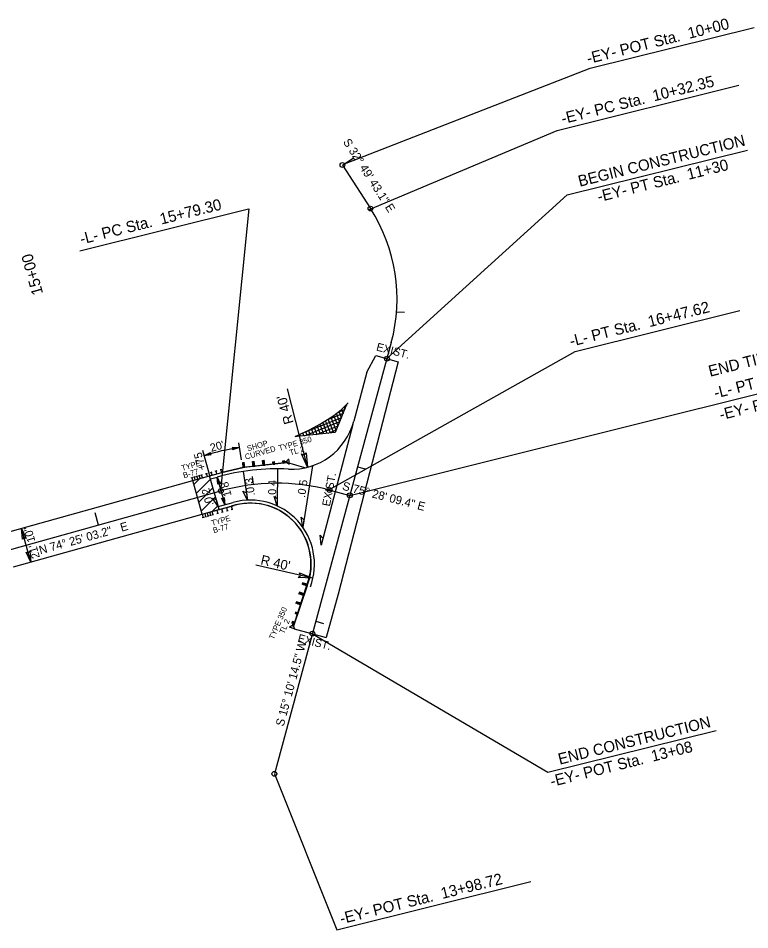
# Model space of a CAD drawing. Extents: x 1030774 to 1032138, y 656382 to 657027.
# Drawn here: x 1031349 to 1031806, y 656458 to 657027 of the extents above; entities that cross this region are included whole.
import ezdxf

# ---------------------------------------------------------------- set-up
doc = ezdxf.new("R2010")
doc.units = 0
for name, color, linetype in [('Default', 7, 'Continuous'), ('Exist Horizontal Alignment', 7, 'Continuous'), ('Exist Horizontal Alignment Direction Label', 7, 'Continuous'), ('Exist Horizontal Alignment Station Label', 7, 'Continuous'), ('Exist Horizontal Alignment Tick Large', 7, 'Continuous'), ('Exist Horizontal Alignment Tick Small', 7, 'Continuous'), ('Prop Approach Slab', 7, 'Continuous'), ('Prop Approach Slab Hatching', 7, 'Continuous'), ('Prop Dimension', 7, 'Continuous'), ('Prop Dimension Text', 7, 'Continuous'), ('Prop EOT', 7, 'Continuous'), ('Prop Guardrail', 7, 'Continuous'), ('Prop Guardrail Anchor Unit CELL', 7, 'Continuous'), ('Prop Horizontal Alignment', 7, 'Continuous'), ('Prop Horizontal Alignment Direction Label', 7, 'Continuous'), ('Prop Horizontal Alignment Station Label', 7, 'Continuous'), ('Prop Horizontal Alignment Tick Label', 7, 'Continuous'), ('Prop Horizontal Alignment Tick Large', 7, 'Continuous'), ('Prop Horizontal Alignment Tick Small', 7, 'Continuous'), ('Prop Paved Shoulder', 7, 'Continuous'), ('Prop Rem of Exist Conc Pvmt', 7, 'Continuous'), ('Prop Roadway Bridge', 7, 'Continuous'), ('Prop Structure Anchor Unit CELL', 7, 'Continuous'), ('Prop Superelevation  Arrow CELL', 7, 'Continuous'), ('Prop Superelevation Label', 7, 'Continuous'), ('Prop Terminator CELL', 7, 'Continuous')]:
    doc.layers.add(name, color=color, linetype=linetype)

msp = doc.modelspace()

# ---------------------------------------------------------------- linework, layer by layer
at = {"layer": 'Default'}
for p, q in [((1031529.48, 656746.41), (1031517.01, 656795.51)), ((1031532.88, 656677.08), (1031497.21, 656685.17))]:
    msp.add_line(p, q, dxfattribs=at)
at = {"layer": 'Exist Horizontal Alignment'}
for p, q in [((1031551.32, 656935.2), (1031568.86, 656908.01)), ((1031581.87, 656824.27), (1031508.83, 656554.91))]:
    msp.add_line(p, q, dxfattribs=at)
msp.add_arc((1031481.33, 656851.54), 104.17, 344.8293, 32.8286, dxfattribs=at)
at = {"layer": 'Exist Horizontal Alignment Station Label'}
for p, q in [((1031706.16, 656995.66), (1031808.52, 657021.19)), ((1031552.58, 656936.01), (1031706.16, 656995.66)), ((1031685.54, 656956.84), (1031799.08, 656985.15)), ((1031567.6, 656907.2), (1031685.54, 656956.84)), ((1031691.81, 656916.51), (1031804.37, 656944.57)), ((1031579.16, 656814.26), (1031691.81, 656916.51)), ((1031532.57, 656642.46), (1031679.65, 656555.88)), ((1031679.65, 656555.88), (1031784.83, 656582.1)), ((1031508.83, 656554.91), (1031547.88, 656457.53)), ((1031547.88, 656457.53), (1031669.1, 656487.76))]:
    msp.add_line(p, q, dxfattribs=at)
for centre in [(1031551.32, 656935.2), (1031568.86, 656908.01), (1031579.16, 656814.26), (1031532.59, 656642.52), (1031508.83, 656554.91)]:
    msp.add_circle(centre, 1.5, dxfattribs=at)
at = {"layer": 'Exist Horizontal Alignment Tick Large'}
msp.add_line((1031551.32, 656935.2), (1031558.05, 656939.54), dxfattribs=at)
at = {"layer": 'Exist Horizontal Alignment Tick Small'}
for p, q in [((1031585.2, 656843.59), (1031590.18, 656843.21)), ((1031560.84, 656746.7), (1031565.66, 656745.39)), ((1031534.67, 656650.19), (1031539.49, 656648.88))]:
    msp.add_line(p, q, dxfattribs=at)
at = {"layer": 'Prop Approach Slab'}
for p, q in [((1031457.91, 656738.11), (1031468.32, 656741.01)), ((1031474.23, 656719.99), (1031468.37, 656741.02)), ((1031463.78, 656717.07), (1031474.19, 656719.97))]:
    msp.add_line(p, q, dxfattribs=at)
at = {"layer": 'Prop Approach Slab Hatching'}
for p, q in [((1031458.57, 656735.74), (1031462.11, 656739.28)), ((1031460.11, 656730.21), (1031468.93, 656739.02)), ((1031461.65, 656724.68), (1031470.47, 656733.49)), ((1031463.2, 656719.15), (1031472.01, 656727.96)), ((1031469.89, 656718.77), (1031473.55, 656722.43))]:
    msp.add_line(p, q, dxfattribs=at)
at = {"layer": 'Prop Dimension'}
for p, q in [((1031472.98, 656740.32), (1031477.81, 656722.98)), ((1031356.66, 656687.2), (1031350.8, 656708.24))]:
    msp.add_line(p, q, dxfattribs=at)
at = {"layer": 'Prop EOT'}
for p, q in [((1031566.68, 656805.86), (1031572.16, 656816.16)), ((1031572.16, 656816.16), (1031586.18, 656812.36)), ((1031586.18, 656812.36), (1031548.7, 656667.1)), ((1031566.68, 656805.86), (1031558.38, 656775.25)), ((1031468.88, 656739.17), (1031472.98, 656740.32)), ((1031473.72, 656721.84), (1031483.13, 656724.46)), ((1031529.38, 656672.34), (1031520.75, 656647.22)), ((1031548.7, 656667.1), (1031541.2, 656640.12)), ((1031521.11, 656645.57), (1031541.2, 656640.12))]:
    msp.add_line(p, q, dxfattribs=at)
for centre, radius, start, end in [((1031519.63, 656785.18), 40, 267.0173, 345.6251), ((1031510.32, 656606.42), 139, 87.0173, 105.5824), ((1031493.88, 656685.93), 40, 339.3432, 105.5824), ((1031493.88, 656685.93), 38, 339.0563, 105.5824)]:
    msp.add_arc(centre, radius, start, end, dxfattribs=at)
at = {"layer": 'Prop Guardrail'}
msp.add_line((1031489.38, 656746.29), (1031475.97, 656743.14), dxfattribs=at)
for centre, radius, start, end in [((1031443.03, 656712.42), 40, 14, 14), ((1031501.41, 656687.22), 40, 119.2937, 119.2937), ((1031493.83, 656686.23), 37.82, 340.0066, 108.4837)]:
    msp.add_arc(centre, radius, start, end, dxfattribs=at)
at = {"layer": 'Prop Guardrail Anchor Unit CELL'}
for p, q in [((1031501.47, 656750.67), (1031502.47, 656750.78)), ((1031502.47, 656750.78), (1031501.64, 656749.17)), ((1031502.8, 656747.77), (1031502.47, 656750.78)), ((1031517.62, 656751.5), (1031516.55, 656750.52)), ((1031517.62, 656751.5), (1031517.93, 656751.53)), ((1031518.25, 656748.61), (1031517.93, 656751.53)), ((1031489.05, 656749.31), (1031490.04, 656749.42)), ((1031489.38, 656746.29), (1031489.05, 656749.31)), ((1031490.21, 656747.91), (1031489.05, 656749.31)), ((1031490.04, 656749.42), (1031489.21, 656747.8)), ((1031489.21, 656747.8), (1031490.21, 656747.91)), ((1031489.21, 656747.8), (1031490.37, 656746.4)), ((1031489.38, 656746.29), (1031490.21, 656747.91)), ((1031489.38, 656746.29), (1031490.37, 656746.4)), ((1031514.72, 656749.07), (1031489.87, 656746.35)), ((1031490.37, 656746.4), (1031490.04, 656749.42)), ((1031495.26, 656749.99), (1031496.25, 656750.1)), ((1031495.59, 656746.98), (1031495.26, 656749.99)), ((1031496.42, 656748.59), (1031495.26, 656749.99)), ((1031496.25, 656750.1), (1031495.42, 656748.48)), ((1031495.42, 656748.48), (1031496.42, 656748.59)), ((1031495.42, 656748.48), (1031496.58, 656747.08)), ((1031495.59, 656746.98), (1031496.42, 656748.59)), ((1031495.59, 656746.98), (1031496.58, 656747.08)), ((1031496.58, 656747.08), (1031496.25, 656750.1)), ((1031501.8, 656747.66), (1031501.47, 656750.67)), ((1031502.63, 656749.27), (1031501.47, 656750.67)), ((1031501.64, 656749.17), (1031502.63, 656749.27)), ((1031501.64, 656749.17), (1031502.8, 656747.77)), ((1031501.8, 656747.66), (1031502.63, 656749.27)), ((1031501.8, 656747.66), (1031502.8, 656747.77)), ((1031507.85, 656749.85), (1031508.84, 656749.96)), ((1031508.01, 656748.34), (1031507.85, 656749.85)), ((1031507.85, 656749.85), (1031509.01, 656748.45)), ((1031508.01, 656748.34), (1031508.84, 656749.96)), ((1031508.01, 656748.34), (1031509.01, 656748.45)), ((1031509.01, 656748.45), (1031508.84, 656749.96)), ((1031514.06, 656750.53), (1031515.06, 656750.64)), ((1031514.23, 656749.02), (1031514.06, 656750.53)), ((1031514.06, 656750.53), (1031515.22, 656749.13)), ((1031514.23, 656749.02), (1031515.06, 656750.64)), ((1031514.23, 656749.02), (1031515.22, 656749.13)), ((1031515.22, 656749.13), (1031515.06, 656750.64)), ((1031516.6, 656750.02), (1031515.14, 656749.85)), ((1031515.22, 656749.14), (1031516.68, 656749.3)), ((1031516.55, 656750.52), (1031516.68, 656749.3)), ((1031516.68, 656749.3), (1031517.95, 656748.57)), ((1031517.95, 656748.57), (1031518.25, 656748.61)), ((1031521.38, 656649.09), (1031529.2, 656672.83)), ((1031526.47, 656674.26), (1031526.16, 656673.31)), ((1031526.16, 656673.31), (1031527.91, 656673.78)), ((1031529.04, 656672.36), (1031526.16, 656673.31)), ((1031529.36, 656673.31), (1031526.47, 656674.26)), ((1031527.6, 656672.83), (1031526.47, 656674.26)), ((1031527.91, 656673.78), (1031527.6, 656672.83)), ((1031529.36, 656673.31), (1031527.6, 656672.83)), ((1031527.91, 656673.78), (1031529.04, 656672.36)), ((1031529.36, 656673.31), (1031529.04, 656672.36)), ((1031524.52, 656668.32), (1031524.2, 656667.37)), ((1031524.2, 656667.37), (1031525.96, 656667.84)), ((1031527.09, 656666.42), (1031524.2, 656667.37)), ((1031527.4, 656667.37), (1031524.52, 656668.32)), ((1031525.64, 656666.89), (1031524.52, 656668.32)), ((1031525.96, 656667.84), (1031525.64, 656666.89)), ((1031527.4, 656667.37), (1031525.64, 656666.89)), ((1031525.96, 656667.84), (1031527.09, 656666.42)), ((1031527.4, 656667.37), (1031527.09, 656666.42)), ((1031522.56, 656662.38), (1031522.25, 656661.43)), ((1031522.25, 656661.43), (1031524, 656661.91)), ((1031525.13, 656660.48), (1031522.25, 656661.43)), ((1031525.44, 656661.43), (1031522.56, 656662.38)), ((1031523.69, 656660.96), (1031522.56, 656662.38)), ((1031524, 656661.91), (1031523.69, 656660.96)), ((1031525.44, 656661.43), (1031523.69, 656660.96)), ((1031524, 656661.91), (1031525.13, 656660.48)), ((1031525.44, 656661.43), (1031525.13, 656660.48)), ((1031522.05, 656655.97), (1031521.73, 656655.02)), ((1031523.49, 656655.5), (1031521.73, 656655.02)), ((1031523.17, 656654.55), (1031521.73, 656655.02)), ((1031523.49, 656655.5), (1031522.05, 656655.97)), ((1031522.05, 656655.97), (1031523.17, 656654.55)), ((1031523.49, 656655.5), (1031523.17, 656654.55)), ((1031520.09, 656650.04), (1031519.78, 656649.09)), ((1031521.53, 656649.56), (1031519.78, 656649.09)), ((1031521.22, 656648.61), (1031519.78, 656649.09)), ((1031520.06, 656647.44), (1031520.53, 656648.84)), ((1031521.53, 656649.56), (1031520.09, 656650.04)), ((1031520.09, 656650.04), (1031521.22, 656648.61)), ((1031521.21, 656648.61), (1031520.75, 656647.22)), ((1031521.53, 656649.56), (1031521.22, 656648.61)), ((1031518.4, 656646.76), (1031518.31, 656646.46)), ((1031521.1, 656645.54), (1031518.31, 656646.46)), ((1031518.4, 656646.76), (1031519.58, 656647.6)), ((1031519.58, 656647.6), (1031520.75, 656647.22)), ((1031520.75, 656647.22), (1031521.19, 656645.83)), ((1031521.19, 656645.83), (1031521.1, 656645.54))]:
    msp.add_line(p, q, dxfattribs=at)
at = {"layer": 'Prop Horizontal Alignment'}
for p, q in [((1031310.74, 656685.73), (1031475.4, 656731.65)), ((1031542.93, 656732.27), (1031556, 656728.88))]:
    msp.add_line(p, q, dxfattribs=at)
msp.add_arc((1031510.32, 656606.42), 130, 75.4693, 105.5824, dxfattribs=at)
at = {"layer": 'Prop Horizontal Alignment Station Label'}
for p, q in [((1031387.2, 656881.59), (1031492.71, 656907.9)), ((1031475.4, 656731.65), (1031493.07, 656907.81)), ((1031696.82, 656818.8), (1031799.62, 656844.43)), ((1031556, 656728.88), (1031931.5, 656822.46)), ((1031542.93, 656732.27), (1031696.82, 656818.8))]:
    msp.add_line(p, q, dxfattribs=at)
for centre in [(1031475.4, 656731.65), (1031543.3, 656732.17), (1031556, 656728.88)]:
    msp.add_circle(centre, 1.5, dxfattribs=at)
at = {"layer": 'Prop Horizontal Alignment Tick Large'}
msp.add_line((1031399.01, 656710.35), (1031396.86, 656718.05), dxfattribs=at)
at = {"layer": 'Prop Horizontal Alignment Tick Small'}
msp.add_line((1031495.7, 656735.6), (1031495.13, 656740.57), dxfattribs=at)
at = {"layer": 'Prop Paved Shoulder'}
for p, q in [((1031516.68, 656749.29), (1031489.38, 656746.29)), ((1031527.81, 656746.06), (1031516.68, 656749.29))]:
    msp.add_line(p, q, dxfattribs=at)
for points in [[(1031468.32, 656741.01), (1031475.97, 656743.14), (1031489.38, 656746.29)], [(1031463.78, 656717.07), (1031483.67, 656722.53)]]:
    msp.add_lwpolyline(points, dxfattribs=at)
at = {"layer": 'Prop Rem of Exist Conc Pvmt'}
for p, q in [((1031553.8, 656785.56), (1031546.9, 656768.15)), ((1031550.47, 656782.25), (1031553.8, 656785.56)), ((1031553.19, 656784.9), (1031554.27, 656785.33)), ((1031553.8, 656785.56), (1031554.88, 656786.75)), ((1031554.16, 656785.08), (1031553.92, 656785.69)), ((1031541.72, 656776), (1031552.04, 656780.13)), ((1031545.95, 656778.76), (1031550.47, 656782.25)), ((1031549.7, 656774.68), (1031547.6, 656779.94)), ((1031549.01, 656781.07), (1031553.15, 656782.73)), ((1031550.82, 656777.28), (1031549.23, 656781.25)), ((1031550.47, 656782.25), (1031552.52, 656784.17)), ((1031552.52, 656784.17), (1031550.47, 656782.25)), ((1031551.93, 656779.88), (1031550.84, 656782.6)), ((1031553.05, 656782.48), (1031552.41, 656784.07)), ((1031525.67, 656767.43), (1031550.92, 656777.53)), ((1031527.74, 656766.11), (1031549.81, 656774.93)), ((1031537.56, 656773.49), (1031543.72, 656777.26)), ((1031541.76, 656767.6), (1031539.05, 656774.38)), ((1031543.83, 656767.83), (1031540.79, 656775.42)), ((1031545.91, 656768.02), (1031542.51, 656776.5)), ((1031543.72, 656777.26), (1031545.95, 656778.76)), ((1031547.47, 656769.48), (1031544.23, 656777.6)), ((1031548.59, 656772.08), (1031545.93, 656778.74)), ((1031521.82, 656765.71), (1031527.18, 656768.1)), ((1031546.9, 656768.15), (1031523.01, 656765.6)), ((1031527.3, 656766.06), (1031526.59, 656767.84)), ((1031527.18, 656768.1), (1031531.21, 656770.1)), ((1031529.37, 656766.28), (1031528.4, 656768.7)), ((1031531.44, 656766.5), (1031530.2, 656769.6)), ((1031531.21, 656770.1), (1031537.56, 656773.49)), ((1031533.5, 656766.72), (1031531.99, 656770.51)), ((1031535.57, 656766.94), (1031533.77, 656771.44)), ((1031535.09, 656766.89), (1031548.69, 656772.33)), ((1031537.63, 656767.16), (1031535.54, 656772.39)), ((1031539.7, 656767.38), (1031537.31, 656773.36)), ((1031542.44, 656767.68), (1031547.58, 656769.73)), ((1031523.01, 656765.6), (1031521.82, 656765.71)), ((1031523.17, 656765.62), (1031522.93, 656766.22)), ((1031525.24, 656765.84), (1031524.76, 656767.03))]:
    msp.add_line(p, q, dxfattribs=at)
at = {"layer": 'Prop Roadway Bridge'}
for p, q in [((1031340.03, 656705.23), (1031457.91, 656738.11)), ((1031463.78, 656717.07), (1031457.91, 656738.11)), ((1031345.9, 656684.2), (1031463.78, 656717.07))]:
    msp.add_line(p, q, dxfattribs=at)
at = {"layer": 'Prop Structure Anchor Unit CELL'}
for p, q in [((1031474.88, 656744.92), (1031475.99, 656745.22)), ((1031475.97, 656743.14), (1031475.43, 656745.07)), ((1031456.82, 656739.88), (1031457.92, 656740.19)), ((1031457.91, 656738.11), (1031457.37, 656740.03)), ((1031457.91, 656738.11), (1031475.97, 656743.14)), ((1031458.33, 656740.3), (1031459.43, 656740.61)), ((1031459.42, 656738.53), (1031458.88, 656740.45)), ((1031459.83, 656740.72), (1031460.93, 656741.03)), ((1031460.92, 656738.95), (1031460.38, 656740.87)), ((1031461.34, 656741.14), (1031462.44, 656741.45)), ((1031462.43, 656739.37), (1031461.89, 656741.29)), ((1031462.84, 656741.56), (1031463.95, 656741.87)), ((1031463.93, 656739.79), (1031463.39, 656741.71)), ((1031465.85, 656742.4), (1031466.96, 656742.71)), ((1031466.94, 656740.63), (1031466.4, 656742.55)), ((1031468.86, 656743.24), (1031469.97, 656743.54)), ((1031469.95, 656741.46), (1031469.41, 656743.39)), ((1031471.87, 656744.08), (1031472.98, 656744.38)), ((1031472.96, 656742.3), (1031472.42, 656744.23)), ((1031463.78, 656717.07), (1031481.84, 656722.1)), ((1031463.78, 656717.07), (1031464.31, 656715.14)), ((1031465.28, 656717.49), (1031465.82, 656715.56)), ((1031466.79, 656717.91), (1031467.32, 656715.98)), ((1031468.29, 656718.33), (1031468.83, 656716.4)), ((1031469.78, 656716.67), (1031470.89, 656716.97)), ((1031469.8, 656718.75), (1031470.33, 656716.82)), ((1031472.79, 656717.5), (1031473.9, 656717.81)), ((1031472.81, 656719.59), (1031473.34, 656717.66)), ((1031475.8, 656718.34), (1031476.91, 656718.65)), ((1031475.82, 656720.42), (1031476.36, 656718.5)), ((1031478.81, 656719.18), (1031479.92, 656719.49)), ((1031478.83, 656721.26), (1031479.37, 656719.34)), ((1031481.82, 656720.02), (1031482.93, 656720.33)), ((1031481.84, 656722.1), (1031482.38, 656720.17)), ((1031463.76, 656714.99), (1031464.87, 656715.3)), ((1031465.27, 656715.41), (1031466.37, 656715.72)), ((1031466.77, 656715.83), (1031467.88, 656716.14)), ((1031468.28, 656716.25), (1031469.38, 656716.55))]:
    msp.add_line(p, q, dxfattribs=at)
at = {"layer": 'Prop Superelevation  Arrow CELL'}
for p, q in [((1031557.85, 656773.22), (1031538.08, 656697.69)), ((1031486.47, 656761.66), (1031488.15, 656751.01)), ((1031510.69, 656745.42), (1031510.63, 656722.25)), ((1031532.55, 656747.33), (1031526.51, 656709.06)), ((1031489.29, 656743.82), (1031492.12, 656725.9))]:
    msp.add_line(p, q, dxfattribs=at)
for points in [[(1031492.12, 656725.9), (1031489.21, 656731.51), (1031491.4, 656730.47)], [(1031510.63, 656722.25), (1031508.66, 656728.26), (1031510.65, 656726.88)], [(1031473.67, 656721.82), (1031470.14, 656727.06), (1031472.43, 656726.28)], [(1031526.51, 656709.06), (1031525.47, 656715.3), (1031527.23, 656713.63)], [(1031538.08, 656697.69), (1031537.51, 656703.99), (1031539.14, 656702.19)]]:
    msp.add_lwpolyline(points, close=True, dxfattribs=at)
at = {"layer": 'Prop Superelevation Label'}
msp.add_line((1031463.82, 656757.14), (1031468.44, 656740.6), dxfattribs=at)
msp.add_arc((1031510.32, 656606.42), 154.06, 98.6619, 107.1812, dxfattribs=at)
at = {"layer": 'Prop Terminator CELL'}
for points in [[(1031482.55, 656758.81), (1031487.12, 656758.72), (1031482.76, 656757.25), (1031483.21, 656758.13)], [(1031469.34, 656754.2), (1031464.81, 656753.61), (1031468.9, 656755.71), (1031468.58, 656754.77)], [(1031528.77, 656755.52), (1031529.48, 656746.41), (1031525.7, 656754.79), (1031527.54, 656754.07)], [(1031473.44, 656735.77), (1031472.98, 656740.32), (1031474.96, 656736.17), (1031474.04, 656736.51)], [(1031477.35, 656727.52), (1031477.81, 656722.98), (1031475.83, 656727.12), (1031476.75, 656726.78)], [(1031351.49, 656701.42), (1031350.8, 656708.24), (1031353.78, 656702.02), (1031352.39, 656702.53)], [(1031355.97, 656694.01), (1031356.66, 656687.2), (1031353.68, 656693.41), (1031355.07, 656692.91)], [(1031524.45, 656680.58), (1031532.88, 656677.08), (1031523.71, 656677.52), (1031525.18, 656678.83)]]:
    msp.add_lwpolyline(points, close=True, dxfattribs=at)

# ---------------------------------------------------------------- texts
at = {"layer": 'Default'}
for s, rotation, p in [("R 40'", 106.0357, (1031520.93, 656774.26)), ("R 40' ", 347.2138, (1031499.86, 656685.86))]:
    msp.add_text(s, height=6, rotation=rotation, dxfattribs=at).set_placement(p)
at = {"layer": 'Exist Horizontal Alignment Direction Label'}
for s, rotation, p in [('S 32%%d 49\' 43.1" E', 302.8286, (1031551.47, 656949.64)), ('S 15%%d 10\' 14.5" W', 74.8293, (1031514.58, 656584.23))]:
    msp.add_text(s, height=5.25, rotation=rotation, dxfattribs=at).set_placement(p)
at = {"layer": 'Exist Horizontal Alignment Station Label'}
for s, p in [('-EY- POT Sta.  10+00', (1031704.97, 656998.26)), ('-EY- PC Sta.  10+32.35', (1031689, 656960.7)), ('BEGIN CONSTRUCTION', (1031699.61, 656921.61)), ('-EY- PT Sta.  11+30', (1031711.57, 656911.97)), ('END CONSTRUCTION', (1031687.11, 656560.61)), ('-EY- POT Sta.  13+08', (1031682.12, 656546.74)), ('-EY- POT Sta.  13+98.72', (1031550.69, 656461.01))]:
    msp.add_text(s, height=7, rotation=14, dxfattribs=at).set_placement(p)
at = {"layer": 'Prop Dimension Text'}
for s, rotation, p in [('EXIST.', 345.4695, (1031572.16, 656819.43)), ("1 8'", 105.5824, (1031482.18, 656728.82)), ('21\' 10"', 105.5824, (1031362.36, 656690.11)), ('EXIST.', 345.4695, (1031523.06, 656637.51))]:
    msp.add_text(s, height=5, rotation=rotation, dxfattribs=at).set_placement(p)
at = {"layer": 'Prop Guardrail Anchor Unit CELL'}
for s, rotation, p in [('TYPE 350', 16, (1031511.99, 656756.61)), ('TL 2', 16, (1031518.85, 656753.8)), ('TYPE 350', 66.5846, (1031508.43, 656638.54)), ('TL 2', 66.5846, (1031514.95, 656642.06))]:
    msp.add_text(s, height=3.5, rotation=rotation, dxfattribs=at).set_placement(p)
at = {"layer": 'Prop Horizontal Alignment Direction Label'}
for s, rotation, p in [('S 75%%d 28\' 09.4" E', 345.4693, (1031550.9, 656732.45)), ('N 74%%d 25\' 03.2"   E', 15.5824, (1031362.58, 656692))]:
    msp.add_text(s, height=5.25, rotation=rotation, dxfattribs=at).set_placement(p)
at = {"layer": 'Prop Horizontal Alignment Station Label'}
for s, p in [('-L- PC Sta.  15+79.30', (1031388.24, 656885.52)), ('-L- PT Sta.  16+47.62', (1031694.24, 656821.7)), ('END TIP PROJECT No.   B-4715', (1031781.05, 656802.93)), ('-L- PT Sta. 16+61.12 =', (1031784.44, 656789.35)), ('-EY- POT Sta. 12+18.47', (1031787.82, 656775.76))]:
    msp.add_text(s, height=7, rotation=14, dxfattribs=at).set_placement(p)
at = {"layer": 'Prop Horizontal Alignment Tick Label'}
msp.add_text('15+00', height=7, rotation=105.5824, dxfattribs=at).set_placement((1031364.4, 656855.04))
at = {"layer": 'Prop Structure Anchor Unit CELL'}
for s, p in [('SHOP', (1031492.29, 656756.35)), ('CURVED', (1031490.95, 656751.11)), ('TYPE', (1031451.29, 656744.13)), ('B-77', (1031452.31, 656739.56)), ('TYPE', (1031469.96, 656709.77)), ('B-77', (1031470.98, 656705.2))]:
    msp.add_text(s, height=3.5, rotation=16, dxfattribs=at).set_placement(p)
at = {"layer": 'Prop Superelevation Label'}
for s, rotation, p in [("20'", 15.5824, (1031469.43, 656755.99)), ('+75', 105.5824, (1031466.16, 656745.29)), ('.0 3', 98.4576, (1031496.74, 656728.96)), ('EXIST.', 79.1501, (1031543.48, 656721.7)), ('.0 4', 89.8471, (1031509.93, 656727.39)), ('.0 5', 81.0324, (1031527.91, 656727.25)), ('.0 2', 105.5824, (1031470.99, 656723.02))]:
    msp.add_text(s, height=5, rotation=rotation, dxfattribs=at).set_placement(p)

doc.saveas('drawing.dxf')
